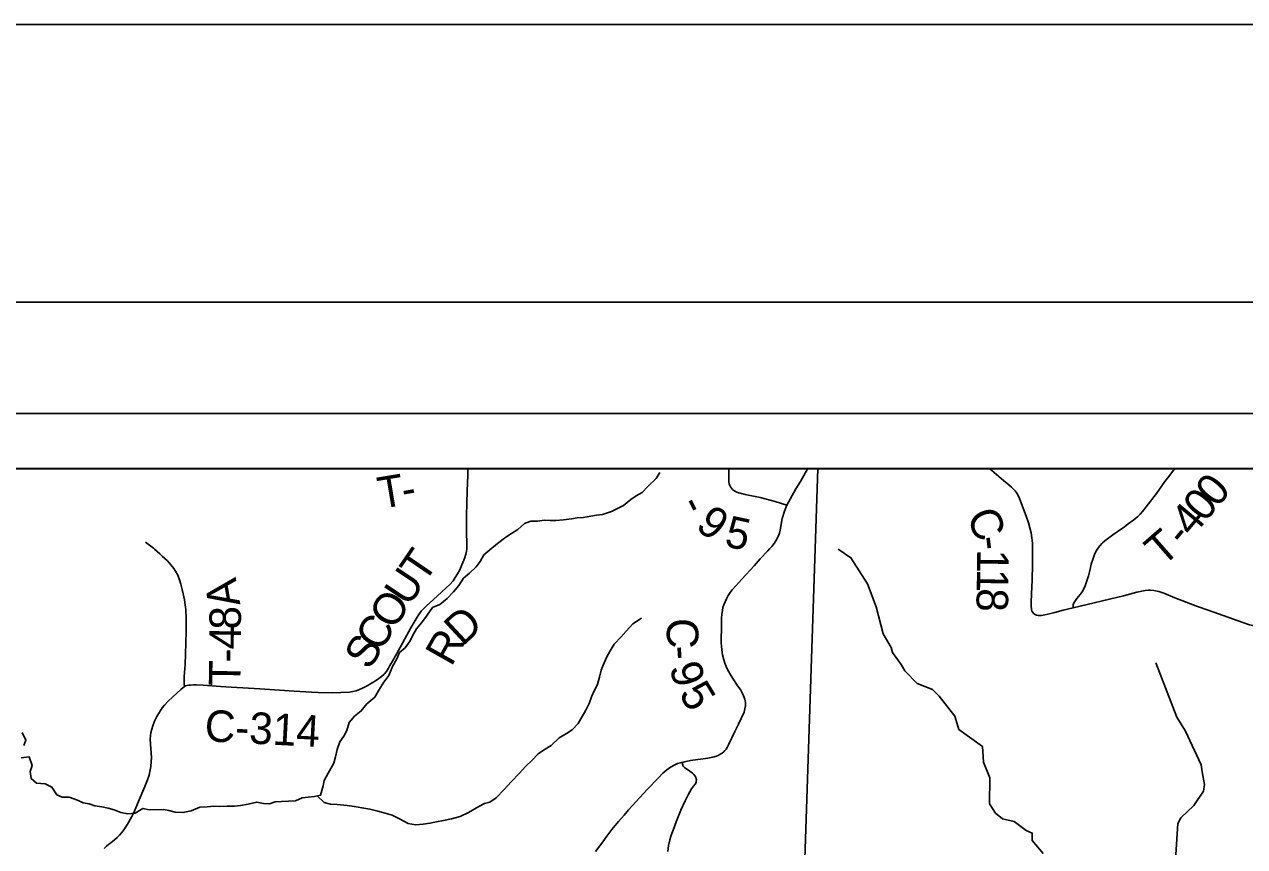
# Model space of a CAD drawing. Extents: x 0 to 34, y 0 to 22.
# Drawn here: x 4.796 to 6.991, y 20.52 to 22 of the extents above; entities that cross this region are included whole.
import ezdxf

# ---------------------------------------------------------------- set-up
doc = ezdxf.new("R2010")
doc.units = 0
for name, color, linetype in [('GM_X_County', 7, 'Continuous'), ('GM_X_County_Road', 7, 'Continuous'), ('GM_X_County_Road_Text', 7, 'Continuous'), ('GM_X_Minor_River', 7, 'Continuous'), ('GM_X_Township', 7, 'Continuous'), ('GM_X_Township_Road', 7, 'Continuous'), ('GM_X_Township_Road_Text', 7, 'Continuous'), ('SH_Border', 7, 'Continuous'), ('SH_Cut_Line', 7, 'Continuous'), ('SH_Data', 7, 'Continuous')]:
    doc.layers.add(name, color=color, linetype=linetype)

msp = doc.modelspace()

# ---------------------------------------------------------------- linework, layer by layer
at = {"layer": 'GM_X_County'}
msp.add_lwpolyline([(7.0736, 21.2003), (2.6013, 21.2003), (2.6013, 14.4003), (9.4013, 14.4003), (9.4013, 21.1598)], dxfattribs=at)
at = {"layer": 'GM_X_County_Road'}
for points in [[(5.0842, 20.8082), (5.0862, 20.8092), (5.0887, 20.8099), (5.0919, 20.8104), (5.0951, 20.8107), (5.1003, 20.8109), (5.1057, 20.811), (5.1181, 20.8104), (5.1335, 20.8092), (5.1489, 20.8081), (5.1685, 20.8069), (5.1994, 20.8054), (5.2199, 20.8041), (5.255, 20.8014), (5.2816, 20.7996), (5.3125, 20.7979), (5.3249, 20.7973), (5.3498, 20.7969), (5.3653, 20.7972), (5.3808, 20.7982), (5.387, 20.7991), (5.393, 20.8005), (5.3989, 20.8025), (5.4046, 20.8049), (5.4129, 20.8091), (5.4209, 20.814), (5.4261, 20.8173), (5.4337, 20.8224), (5.4387, 20.8261), (5.4433, 20.8302), (5.4475, 20.8354), (5.4512, 20.8413), (5.4537, 20.8457), (5.4585, 20.8538), (5.4692, 20.8728), (5.4917, 20.9136), (5.4994, 20.9272), (5.5045, 20.9359), (5.5101, 20.9435), (5.5199, 20.9536), (5.5388, 20.9708), (5.5551, 20.9859), (5.5616, 20.9919), (5.5674, 20.9985), (5.5713, 21.0042), (5.5753, 21.0107), (5.5793, 21.0179), (5.5833, 21.0271), (5.587, 21.0354), (5.5888, 21.0405), (5.5906, 21.0464), (5.5918, 21.0516), (5.5922, 21.0552), (5.5924, 21.0609), (5.5922, 21.068), (5.5916, 21.0828), (5.5915, 21.0965), (5.5916, 21.1151), (5.5922, 21.1381), (5.593, 21.1606), (5.5938, 21.1878), (5.5939, 21.2003)], [(6.5321, 21.2003), (6.5365, 21.1969), (6.5579, 21.179), (6.5674, 21.171), (6.572, 21.1669), (6.5765, 21.1625), (6.5785, 21.1601), (6.5804, 21.1577), (6.5821, 21.1551), (6.5852, 21.1496), (6.5876, 21.1435), (6.592, 21.1324), (6.5986, 21.1148), (6.6026, 21.103), (6.6052, 21.094), (6.6073, 21.0849), (6.6087, 21.0756), (6.6096, 21.0663), (6.6098, 21.0601), (6.6099, 21.0508), (6.6101, 21.0446), (6.61, 21.0322), (6.6099, 21.0198), (6.6094, 21.0075), (6.609, 20.9982), (6.6088, 20.989), (6.6083, 20.9735), (6.6077, 20.9611), (6.6076, 20.9518), (6.6078, 20.9488), (6.6081, 20.946), (6.6086, 20.944), (6.6092, 20.9429), (6.6105, 20.9411), (6.6125, 20.939), (6.6135, 20.9382), (6.6146, 20.9377), (6.617, 20.9367), (6.6198, 20.9361), (6.6228, 20.9358), (6.6258, 20.936), (6.6348, 20.9378), (6.6498, 20.9414), (6.6648, 20.9454), (6.683, 20.95)], [(5.9806, 20.672), (5.9866, 20.6733), (5.9943, 20.6747), (6.0077, 20.6766), (6.0172, 20.678), (6.0257, 20.6792), (6.0348, 20.6811), (6.0415, 20.683), (6.0442, 20.6839), (6.0464, 20.6851), (6.0493, 20.6869), (6.0517, 20.6884), (6.0544, 20.6904), (6.0564, 20.6928), (6.0588, 20.6956), (6.0607, 20.6984), (6.0632, 20.7032), (6.0741, 20.7269), (6.0812, 20.7406), (6.0909, 20.7622), (6.0925, 20.7677), (6.0934, 20.7732), (6.0935, 20.7763), (6.0933, 20.7793), (6.0928, 20.7823), (6.0921, 20.7853), (6.0901, 20.7911), (6.0876, 20.7968), (6.0851, 20.8013), (6.0788, 20.8103), (6.0707, 20.8223), (6.0657, 20.8303), (6.0613, 20.8385), (6.0586, 20.8442), (6.0563, 20.85), (6.0544, 20.8559), (6.0522, 20.865), (6.0507, 20.8743), (6.0501, 20.8805), (6.0498, 20.8868), (6.0501, 20.9199), (6.0506, 20.9314), (6.0511, 20.9383), (6.0519, 20.9452), (6.053, 20.9503), (6.0545, 20.9552), (6.0569, 20.9608), (6.0593, 20.9662), (6.0626, 20.972), (6.066, 20.9772), (6.0698, 20.9821), (6.0761, 20.9893), (6.0872, 21.0013), (6.109, 21.0256), (6.1199, 21.0382), (6.1336, 21.0524), (6.1369, 21.0558), (6.1406, 21.0603), (6.1451, 21.0657), (6.15, 21.0735), (6.1534, 21.0811), (6.1545, 21.0839), (6.1561, 21.0898), (6.1596, 21.1106), (6.1639, 21.124), (6.1679, 21.1346)], [(4.94, 20.5166), (4.944, 20.5207), (4.9482, 20.5242), (4.9516, 20.527), (4.9582, 20.5323), (4.9629, 20.5362), (4.9674, 20.5406), (4.9715, 20.5454), (4.9753, 20.5503), (4.9788, 20.5555), (4.9837, 20.5635), (4.9896, 20.5744), (4.9937, 20.5828), (4.9999, 20.597), (5.0047, 20.6085), (5.0095, 20.6199), (5.0131, 20.6284), (5.0176, 20.64), (5.0205, 20.6488), (5.0227, 20.6579), (5.0237, 20.664), (5.0245, 20.6733), (5.0247, 20.6795), (5.0243, 20.6889), (5.0231, 20.7043), (5.0227, 20.7134), (5.023, 20.7195), (5.0239, 20.7255), (5.0252, 20.7315), (5.027, 20.7374), (5.0304, 20.7459), (5.0344, 20.7542), (5.0391, 20.7622), (5.0442, 20.7698), (5.0481, 20.7744), (5.0544, 20.781), (5.0634, 20.7895), (5.0779, 20.8026), (5.0842, 20.8082)], [(5.8239, 20.511), (5.8367, 20.5287), (5.844, 20.5387), (5.8533, 20.551), (5.865, 20.5654), (5.8751, 20.5766), (5.8833, 20.586), (5.9169, 20.6226), (5.9362, 20.643), (5.945, 20.6519), (5.9519, 20.6582), (5.9569, 20.662), (5.9596, 20.6637), (5.9651, 20.6665), (5.971, 20.6693), (5.976, 20.6707), (5.9806, 20.672)]]:
    msp.add_lwpolyline(points, dxfattribs=at)
at = {"layer": 'GM_X_Minor_River'}
for points in [[(5.568, 20.9783), (5.5778, 20.9901), (5.586, 21.003), (5.597, 21.0122), (5.609, 21.0236), (5.6162, 21.0331), (5.623, 21.0449), (5.6335, 21.054), (5.6471, 21.0658), (5.6626, 21.0769), (5.6728, 21.0838), (5.6837, 21.091), (5.6958, 21.1017), (5.7075, 21.1055), (5.7192, 21.1055), (5.7321, 21.1075), (5.7419, 21.1071), (5.7525, 21.1068), (5.7662, 21.108), (5.7805, 21.1099), (5.7904, 21.1115), (5.8021, 21.1126), (5.815, 21.1146), (5.8255, 21.1165), (5.8365, 21.1177), (5.8524, 21.1234), (5.8743, 21.1341), (5.8871, 21.1448), (5.8969, 21.1513), (5.9075, 21.1574), (5.9177, 21.168), (5.9328, 21.1825), (5.9395, 21.1932)], [(6.6288, 20.5073), (6.6094, 20.5308), (6.6094, 20.5444), (6.5987, 20.5489), (6.5771, 20.5652), (6.5559, 20.5697), (6.543, 20.5802), (6.5323, 20.5969), (6.5328, 20.6439), (6.5214, 20.672), (6.5197, 20.7004), (6.4776, 20.731), (6.4699, 20.7545), (6.4421, 20.7908), (6.4299, 20.8025), (6.4026, 20.8135), (6.3802, 20.8365), (6.3733, 20.8479), (6.3581, 20.8691), (6.3554, 20.8786), (6.3409, 20.9028), (6.3286, 20.9517), (6.3133, 20.993), (6.2832, 21.0399), (6.26, 21.0554)], [(4.7906, 20.6798), (4.8046, 20.6817), (4.8103, 20.6662), (4.8066, 20.6551), (4.8085, 20.6423), (4.818, 20.6339), (4.8336, 20.6329), (4.8457, 20.6272), (4.8548, 20.6132), (4.8643, 20.6091), (4.8768, 20.6087), (4.8916, 20.6035), (4.9018, 20.5989), (4.9128, 20.5971), (4.9227, 20.5933), (4.9356, 20.5915), (4.9469, 20.5889), (4.9575, 20.5862), (4.9697, 20.5813), (4.9826, 20.5787), (4.9958, 20.5803), (5.0094, 20.5887), (5.0208, 20.5864), (5.0465, 20.5865), (5.0563, 20.585), (5.0673, 20.5821), (5.0813, 20.5813), (5.0965, 20.5844), (5.1116, 20.5909), (5.1252, 20.5917), (5.1369, 20.5925), (5.1479, 20.5922), (5.1608, 20.5926), (5.174, 20.593), (5.185, 20.5938), (5.199, 20.5965), (5.2141, 20.6), (5.2266, 20.5974), (5.2369, 20.5967), (5.2471, 20.6005), (5.2588, 20.6009), (5.2838, 20.6021), (5.2959, 20.6075), (5.3065, 20.6087), (5.3182, 20.6102), (5.3292, 20.6125), (5.334, 20.6292), (5.3355, 20.6387), (5.343, 20.6524), (5.3528, 20.6699), (5.3561, 20.6813), (5.3591, 20.6946), (5.3636, 20.7086), (5.3707, 20.7189), (5.3764, 20.7292), (5.3805, 20.7436), (5.3903, 20.755), (5.4023, 20.7642), (5.4125, 20.7767), (5.4265, 20.7889), (5.4336, 20.8014), (5.443, 20.8159), (5.4516, 20.8281), (5.4584, 20.844), (5.4663, 20.8581), (5.4708, 20.8691), (5.4813, 20.8779), (5.4904, 20.8904), (5.4952, 20.9007), (5.5016, 20.9117), (5.5107, 20.9227), (5.5208, 20.9368), (5.5306, 20.9501), (5.5435, 20.9558), (5.557, 20.9665), (5.568, 20.9783)], [(5.3227, 20.6112), (5.3353, 20.5993), (5.347, 20.5963), (5.3588, 20.5956), (5.3769, 20.5941), (5.3898, 20.5919), (5.4035, 20.59), (5.4179, 20.5874), (5.4319, 20.5837), (5.4455, 20.5803), (5.4577, 20.5765), (5.4709, 20.5698), (5.4869, 20.5615), (5.4997, 20.5592), (5.5134, 20.5604), (5.5259, 20.562), (5.5376, 20.5643), (5.5501, 20.567), (5.5644, 20.5701), (5.5799, 20.5739), (5.5951, 20.5812), (5.6139, 20.5919), (5.6238, 20.5976), (5.6336, 20.5999), (5.6449, 20.6079), (5.6589, 20.6224), (5.6724, 20.6372), (5.6864, 20.6513), (5.6984, 20.6646), (5.709, 20.6749), (5.7203, 20.6871), (5.7331, 20.6955), (5.7437, 20.702), (5.7584, 20.716), (5.7716, 20.7237), (5.7818, 20.7302), (5.7923, 20.7416), (5.7999, 20.7541), (5.8062, 20.7655), (5.8123, 20.7773), (5.8167, 20.7898), (5.8216, 20.8016), (5.8272, 20.8119), (5.831, 20.8248), (5.8339, 20.8373), (5.8373, 20.8468), (5.8437, 20.8601), (5.8501, 20.8723), (5.8572, 20.8841), (5.87, 20.8978), (5.8787, 20.908), (5.8907, 20.921), (5.9066, 20.9309)], [(6.8124, 20.3022), (6.8144, 20.3091), (6.8041, 20.3254), (6.8029, 20.3451), (6.8078, 20.3547), (6.8213, 20.3672), (6.8394, 20.4064), (6.8595, 20.474), (6.8674, 20.4964), (6.8716, 20.5616), (6.8769, 20.5715), (6.9002, 20.594), (6.9175, 20.6195), (6.9194, 20.6316), (6.9151, 20.6547), (6.9132, 20.6673), (6.8853, 20.7275), (6.8693, 20.7532), (6.8317, 20.8506)], [(4.7923, 20.7253), (4.7988, 20.7116), (4.7954, 20.7018)]]:
    msp.add_lwpolyline(points, dxfattribs=at)
at = {"layer": 'GM_X_Township'}
msp.add_line((7.0736, 21.2003), (6.2234, 21.2003), dxfattribs=at)
for points in [[(6.2234, 21.2003), (2.6013, 21.2003), (2.6013, 16.5379)], [(2.6013, 16.5379), (2.8688, 16.5234), (3.5006, 16.5009), (4.2928, 16.4705), (5.2983, 16.434), (6.0664, 16.4042), (6.0778, 16.7443), (6.0911, 17.2548), (6.11, 17.7459), (6.1473, 18.845), (6.1717, 19.6397), (6.1731, 19.6616), (6.1731, 19.6818), (6.1733, 19.6859), (6.2234, 21.2003)], [(6.2234, 21.2003), (6.1733, 19.6859), (6.1731, 19.6818), (6.1731, 19.6616), (6.1717, 19.6397), (6.1473, 18.845), (6.11, 17.7459), (6.0911, 17.2548), (6.0778, 16.7443), (6.0664, 16.4042), (6.0598, 16.2379), (6.2085, 16.2337), (6.3056, 16.228), (6.5048, 16.2253), (7.5772, 16.1862), (7.7357, 16.1804), (8.4842, 16.1527), (8.5405, 16.1503), (9.1818, 16.131), (9.4013, 16.1226)]]:
    msp.add_lwpolyline(points, dxfattribs=at)
at = {"layer": 'GM_X_Township_Road'}
for points in [[(6.1679, 21.1346), (6.147, 21.1409), (6.1291, 21.146), (6.1202, 21.1483), (6.1111, 21.1502), (6.0931, 21.1539), (6.0841, 21.1559), (6.0811, 21.1568), (6.0782, 21.1578), (6.0754, 21.1591), (6.0727, 21.1607), (6.0703, 21.1627), (6.0683, 21.1649), (6.0666, 21.1675), (6.0652, 21.1702), (6.0643, 21.1732), (6.0638, 21.1762), (6.0635, 21.1793), (6.0633, 21.1855), (6.0637, 21.2003)], [(6.1679, 21.1346), (6.1738, 21.1456), (6.1839, 21.1637), (6.1922, 21.1772), (6.2015, 21.1933), (6.2055, 21.2003)], [(6.683, 20.95), (6.6829, 20.9539), (6.683, 20.9555), (6.6835, 20.9569), (6.6843, 20.959), (6.686, 20.9614), (6.6897, 20.9663), (6.6954, 20.9736), (6.6989, 20.9787), (6.7019, 20.984), (6.7045, 20.9896), (6.7077, 20.9983), (6.7104, 21.0071), (6.7134, 21.0191), (6.7155, 21.0281), (6.7183, 21.0369), (6.7214, 21.0457), (6.724, 21.0513), (6.7272, 21.0566), (6.7309, 21.0615), (6.7351, 21.066), (6.7397, 21.0702), (6.7469, 21.076), (6.7544, 21.0814), (6.7697, 21.0917), (6.7747, 21.0952), (6.7822, 21.1007), (6.792, 21.1082), (6.7991, 21.1142), (6.8035, 21.1186), (6.8076, 21.1232), (6.8142, 21.1318), (6.833, 21.1558), (6.848, 21.1774), (6.8526, 21.1834), (6.8567, 21.1885), (6.8635, 21.1973), (6.8675, 21.2003)], [(5.0842, 20.8082), (5.0839, 20.8115), (5.0838, 20.8174), (5.0838, 20.8264), (5.0854, 20.8479), (5.0859, 20.8666), (5.0864, 20.8869), (5.087, 20.9072), (5.0873, 20.9312), (5.0865, 20.9467), (5.0856, 20.9553), (5.0842, 20.9644), (5.082, 20.9751), (5.08, 20.983), (5.0778, 20.9921), (5.0753, 21.0003), (5.0721, 21.0083), (5.0682, 21.0158), (5.0651, 21.0205), (5.0597, 21.0274), (5.0536, 21.0343), (5.0443, 21.0429), (5.0398, 21.0471), (5.0352, 21.0512), (5.0305, 21.0551), (5.0282, 21.057), (5.0258, 21.0589), (5.0235, 21.0608), (5.0188, 21.0644), (5.0164, 21.0661), (5.0138, 21.0677)], [(7.021, 20.9175), (7.0206, 20.9175), (7.0123, 20.917), (7.0092, 20.9172), (7.0062, 20.9178), (7.0002, 20.9194), (6.9885, 20.9235), (6.9359, 20.9421), (6.9241, 20.946), (6.9065, 20.9521), (6.8862, 20.9599), (6.8661, 20.9679), (6.8459, 20.976), (6.8371, 20.979), (6.8311, 20.9806), (6.8281, 20.9811), (6.8219, 20.9815), (6.8188, 20.9815), (6.8126, 20.9808), (6.8065, 20.9797), (6.7974, 20.9777), (6.7734, 20.9715), (6.683, 20.95)], [(5.9536, 20.5114), (5.9551, 20.5219), (5.9573, 20.5324), (5.9599, 20.5406), (5.9631, 20.5495), (5.9688, 20.5644), (5.9737, 20.5767), (5.9772, 20.5853), (5.9848, 20.6021), (5.9889, 20.6105), (5.9902, 20.6133), (5.9932, 20.6187), (5.9966, 20.6238), (6.0001, 20.6288), (6.0027, 20.6323), (6.0047, 20.6356), (6.005, 20.6377), (6.0051, 20.64), (6.0047, 20.6422), (6.004, 20.6449), (6.0026, 20.6475), (6.0007, 20.6499), (5.9984, 20.652), (5.996, 20.6538), (5.991, 20.6573), (5.9861, 20.6607), (5.9838, 20.6626), (5.9816, 20.6647), (5.9809, 20.6661), (5.9805, 20.6673), (5.9804, 20.669), (5.9806, 20.672)]]:
    msp.add_lwpolyline(points, dxfattribs=at)
at = {"layer": 'SH_Border'}
msp.add_lwpolyline([(2, 21.5), (33.5, 21.5), (33.5, 0.5), (2, 0.5)], close=True, dxfattribs=at)
at = {"layer": 'SH_Cut_Line'}
msp.add_lwpolyline([(0, 0), (34, 0), (34, 22), (0, 22)], close=True, dxfattribs=at)
at = {"layer": 'SH_Data'}
for p, q in [((2.5, 21.2997), (9.5, 21.2997)), ((2.6, 21.1997), (9.4, 21.1997))]:
    msp.add_line(p, q, dxfattribs=at)

# ---------------------------------------------------------------- texts
at = {"layer": 'GM_X_County_Road_Text'}
for s, height, rotation, p in [('C', 0.0568, 293.1489, (6.4904, 21.1152)), ('-', 0.0568, 276.9798, (6.5077, 21.0764)), ('T', 0.0568, 55.7204, (5.5153, 20.9916)), ('1', 0.0568, 269.3182, (6.5104, 21.0552)), ('U', 0.0568, 56.317, (5.4876, 20.9502)), ('1', 0.0568, 269.1881, (6.51, 21.0203)), ('O', 0.0568, 57.7548, (5.4612, 20.9082)), ('8', 0.0568, 269.1777, (6.5095, 20.9853)), ('D', 0.0568, 42.8307, (5.5843, 20.8793)), ('C', 0.0568, 58.5242, (5.4369, 20.8686)), ('C', 0.0568, 269.3521, (5.9523, 20.9316)), ('S', 0.0568, 58.5375, (5.4169, 20.8359)), ('R', 0.0568, 60.4715, (5.5642, 20.8423)), ('-', 0.0568, 273.8029, (5.9519, 20.8801)), ('9', 0.0568, 286.7614, (5.9559, 20.8431)), ('5', 0.0568, 301.2278, (5.9724, 20.7953)), ('C-314', 0.05682, 357.0568, (5.1196, 20.7097))]:
    msp.add_text(s, height=height, rotation=rotation, dxfattribs=at).set_placement(p)
at = {"layer": 'GM_X_Township_Road_Text'}
for s, rotation, p in [('T', 9.5689, (5.4371, 21.1277)), ('0', 50.0213, (6.9419, 21.1286)), ('-', 9.7923, (5.4791, 21.1348)), ('0', 50.0178, (6.9195, 21.102)), ('-', 296.179, (5.973, 21.1363)), ('9', 322.7739, (6.0014, 21.0933)), ('4', 49.9936, (6.8972, 21.0754)), ('5', 347.9037, (6.0538, 21.0609)), ('T', 41.1158, (6.8435, 21.0224)), ('-', 50.5673, (6.8826, 21.0577)), ('A', 99.7831, (5.1848, 20.9559)), ('8', 90.4826, (5.186, 20.9109)), ('4', 89.3392, (5.1856, 20.8746)), ('-', 89.2359, (5.1853, 20.8512)), ('T', 89.2157, (5.1847, 20.8087))]:
    msp.add_text(s, height=0.0568, rotation=rotation, dxfattribs=at).set_placement(p)

doc.saveas('drawing.dxf')
